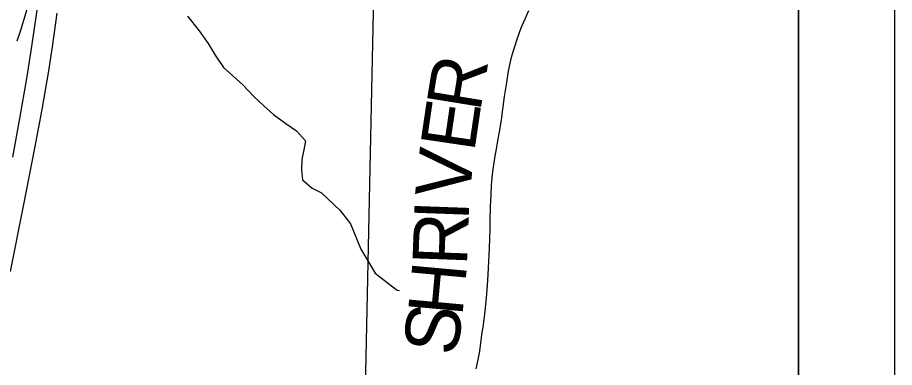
# Model space of a CAD drawing. Extents: x 0 to 34, y 0 to 22.
# Drawn here: x 8.087 to 9, y 19.939 to 20.304 of the extents above; entities that cross this region are included whole.
import ezdxf

# ---------------------------------------------------------------- set-up
doc = ezdxf.new("R2010")
doc.units = 0
for name, color, linetype in [('GM_X_Corporation', 7, 'Continuous'), ('GM_X_County_Road', 7, 'Continuous'), ('GM_X_County_Road_Text', 7, 'Continuous'), ('GM_X_Interchange_Ramps', 7, 'Continuous'), ('GM_X_Interstate_Route', 7, 'Continuous'), ('GM_X_Minor_River', 7, 'Continuous'), ('SH_Data', 7, 'Continuous')]:
    doc.layers.add(name, color=color, linetype=linetype)

msp = doc.modelspace()

# ---------------------------------------------------------------- linework, layer by layer
at = {"layer": 'GM_X_Corporation'}
for points in [[(7.97945, 19.53536), (8.40332, 19.52682), (8.9, 19.5152), (8.9, 20.9), (2.1, 20.9)], [(7.97945, 19.53536), (8.40332, 19.52682), (8.9, 19.5152), (8.9, 20.9), (3.38863, 20.9)]]:
    msp.add_lwpolyline(points, dxfattribs=at)
for points in [[(8.46216, 20.53916), (8.44047, 19.52563), (7.42308, 19.55263), (7.44368, 20.56496)], [(8.9, 19.51485), (8.9, 20.52554), (8.46216, 20.53916), (8.44047, 19.52563)]]:
    msp.add_lwpolyline(points, close=True, dxfattribs=at)
at = {"layer": 'GM_X_County_Road'}
msp.add_lwpolyline([(8.56465, 19.93792), (8.56638, 19.94578), (8.5682, 19.95617), (8.56946, 19.96477), (8.57058, 19.97276), (8.57126, 19.97768), (8.57179, 19.98135), (8.5735, 19.99485), (8.57391, 19.9979), (8.57419, 20.00099), (8.57465, 20.0053), (8.57516, 20.01149), (8.57552, 20.01582), (8.57622, 20.02509), (8.57701, 20.03561), (8.57742, 20.04306), (8.5777, 20.04986), (8.57798, 20.05544), (8.57865, 20.07281), (8.57906, 20.08398), (8.57925, 20.09265), (8.57962, 20.10688), (8.57997, 20.11922), (8.58044, 20.12906), (8.58142, 20.14073), (8.58279, 20.15047), (8.5843, 20.15957), (8.58556, 20.16681), (8.58715, 20.17529), (8.58941, 20.18864), (8.59075, 20.19717), (8.59407, 20.2216), (8.59628, 20.23626), (8.59831, 20.24786), (8.60005, 20.25637), (8.60208, 20.26482), (8.6043, 20.27259), (8.60775, 20.28322), (8.61144, 20.29312), (8.61407, 20.29943), (8.61948, 20.3113)], dxfattribs=at)
at = {"layer": 'GM_X_Interchange_Ramps'}
msp.add_lwpolyline([(8.12606, 20.47545), (8.12459, 20.47082), (8.12368, 20.46796), (8.1229, 20.46524), (8.122, 20.46175), (8.12126, 20.45726), (8.12047, 20.4504), (8.11777, 20.42132), (8.11493, 20.39726), (8.11312, 20.38435), (8.11005, 20.36722), (8.10606, 20.34838), (8.10043, 20.32609), (8.09562, 20.30873), (8.08964, 20.28913), (8.0864, 20.27907)], dxfattribs=at)
at = {"layer": 'GM_X_Interstate_Route'}
for points in [[(8.08207, 20.15828), (8.08957, 20.19859), (8.09674, 20.24023), (8.10142, 20.26905), (8.10723, 20.30902), (8.11314, 20.35211), (8.11583, 20.3737), (8.12198, 20.43053), (8.12478, 20.4596), (8.12606, 20.47545), (8.12743, 20.49243), (8.13009, 20.53024), (8.13185, 20.56126), (8.13326, 20.59355), (8.13457, 20.63019), (8.13542, 20.66634), (8.1355, 20.66996), (8.1359, 20.70787), (8.13579, 20.74454), (8.13528, 20.7781), (8.13391, 20.82656), (8.13255, 20.86009), (8.13061, 20.89671), (8.13038, 20.9)], [(8.07984, 20.03906), (8.09376, 20.10912), (8.10521, 20.16763), (8.11259, 20.20794), (8.11952, 20.24833), (8.12348, 20.27347), (8.12842, 20.30851)]]:
    msp.add_lwpolyline(points, dxfattribs=at)
at = {"layer": 'GM_X_Minor_River'}
msp.add_lwpolyline([(8.26385, 20.30533), (8.27608, 20.28992), (8.28564, 20.27677), (8.29293, 20.26472), (8.30136, 20.25192), (8.31126, 20.24293), (8.32155, 20.23357), (8.33262, 20.22194), (8.34367, 20.21145), (8.35357, 20.20284), (8.36651, 20.1935), (8.37754, 20.18566), (8.3867, 20.17553), (8.38527, 20.16604), (8.38309, 20.15579), (8.38281, 20.14518), (8.38366, 20.13458), (8.39394, 20.12597), (8.40343, 20.12115), (8.42287, 20.10279), (8.43357, 20.08888), (8.43936, 20.0753), (8.44439, 20.06248), (8.45167, 20.05043), (8.45935, 20.03763), (8.47191, 20.02791), (8.48218, 20.01968), (8.48483, 20.01933)], dxfattribs=at)
at = {"layer": 'SH_Data'}
for p, q in [((9, 21), (9, 14)), ((8.9, 20.9), (8.9, 14.1))]:
    msp.add_line(p, q, dxfattribs=at)

# ---------------------------------------------------------------- texts
at = {"layer": 'GM_X_County_Road_Text'}
for s, rotation, p in [('R', 80.76064, (8.56865, 20.20461)), ('E', 81.60898, (8.56248, 20.16279)), ('V', 84.05524, (8.55738, 20.11369)), ('I', 87.91348, (8.55661, 20.09138)), ('R', 87.88356, (8.55488, 20.04471)), ('H', 84.77414, (8.55011, 19.99156)), ('S', 81.32391, (8.54388, 19.94996))]:
    msp.add_text(s, height=0.05682, rotation=rotation, dxfattribs=at).set_placement(p)

doc.saveas('drawing.dxf')
